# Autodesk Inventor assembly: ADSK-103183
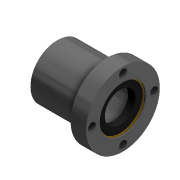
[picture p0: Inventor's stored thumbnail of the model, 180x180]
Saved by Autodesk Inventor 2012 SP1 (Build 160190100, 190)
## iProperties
Shininess: 0.0
Created: 2000-07
Part Number: ADSK-103183
Document SubType Name: Assembly
Stock Number: ADSK-103183
Density: 0.0
Volumn: 0.0
Area: 0.0
PropertySet Name: Model Information
Control State: 0
Master: False
Checked Out: False
Author: gao
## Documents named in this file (4)
- D:\AOTC\Autodesk Inventor 2012 Essential for New Users\Autodesk Inventor 2012 Essentials - Project Files\Learning\Workspace\Sub-Assemblies\ADSK-103183.iam
- D:\AOTC\Autodesk Inventor 2012 Essential for New Users\Autodesk Inventor 2012 Essentials - Project Files\Learning\Workspace\Parts\ADSK-103289.ipt
- D:\AOTC\Autodesk Inventor 2012 Essential for New Users\Autodesk Inventor 2012 Essentials - Project Files\Learning\Workspace\Parts\ADSK-103290.ipt
- D:\AOTC\Autodesk Inventor 2012 Essential for New Users\Autodesk Inventor 2012 Essentials - Project Files\Learning\Workspace\Parts\ADSK-103291.ipt
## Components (5 placed, 3 different names)
1. ADSK-103290:1 — Insert:1, Insert:3
2. ADSK-103289:1 — Insert:3, Insert:4
3. ADSK-103289:2 — Insert:1, Insert:2
4. ADSK-103291:1 — Insert:2
5. ADSK-103291:2 — Insert:4
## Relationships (4: Insert 4)
- Insert:1: ADSK-103290:1 ↔ ADSK-103289:2
- Insert:2: ADSK-103289:2 ↔ ADSK-103291:1
- Insert:3: ADSK-103290:1 ↔ ADSK-103289:1
- Insert:4: ADSK-103289:1 ↔ ADSK-103291:2
